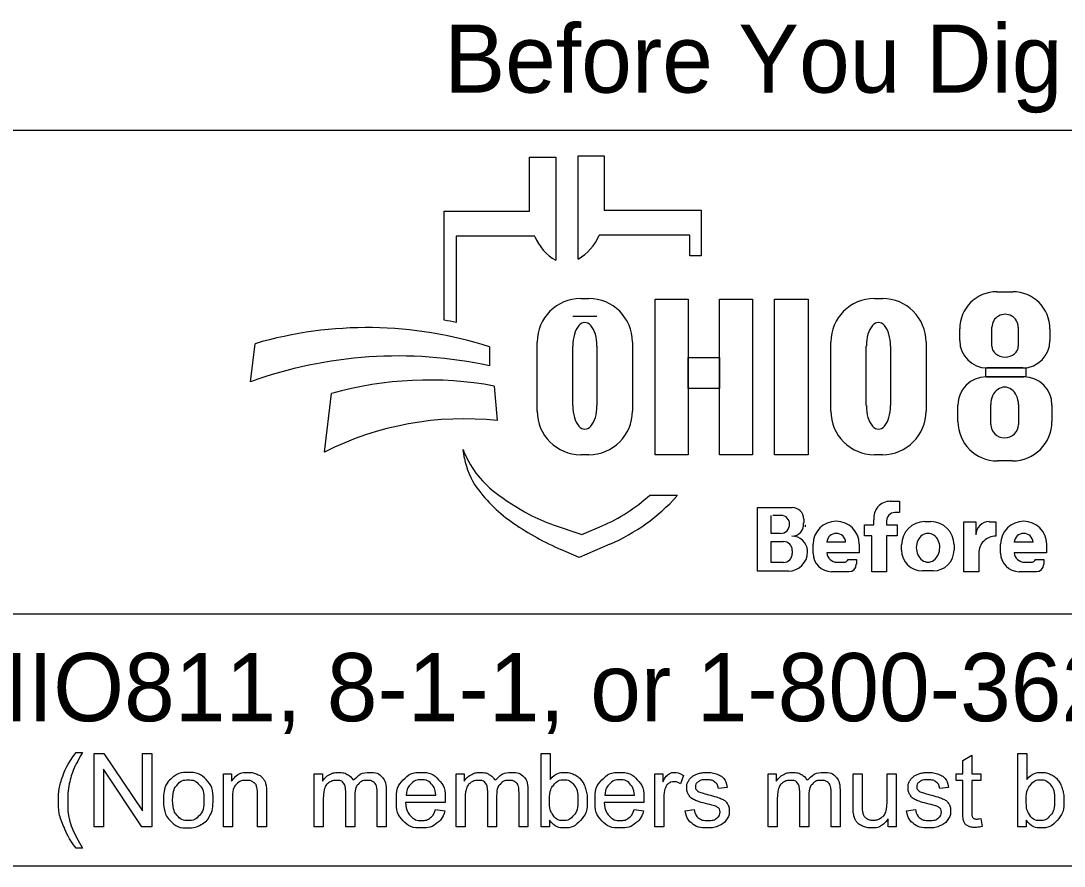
# Model space of a CAD drawing. Extents: x 0 to 34, y 0 to 22.
# Drawn here: x 2.689 to 4.831, y 2.143 to 3.88 of the extents above; entities that cross this region are included whole.
import ezdxf

# ---------------------------------------------------------------- set-up
doc = ezdxf.new("R2010")
doc.units = 0
doc.layers.add('GM_X_Minor_Lake', color=7, linetype='Continuous')
doc.layers.add('GM_X_Minor_Lake_Text', color=7, linetype='Continuous')

msp = doc.modelspace()

# ---------------------------------------------------------------- linework, layer by layer
at = {"layer": 'GM_X_Minor_Lake'}
for p, q in [((3.8329, 3.39), (3.8329, 3.6021)), ((3.8329, 3.6021), (3.8865, 3.6021)), ((3.8865, 3.6021), (3.8865, 3.4906)), ((3.7335, 3.4883), (3.7335, 3.5998)), ((3.7335, 3.5998), (3.7872, 3.5998)), ((3.7872, 3.5998), (3.7872, 3.3877)), ((3.5576, 3.2644), (3.5576, 3.4883)), ((3.5576, 3.4883), (3.7335, 3.4883)), ((3.8865, 3.4906), (4.0857, 3.4906)), ((4.0857, 3.4906), (4.0857, 3.3968)), ((3.5828, 3.4369), (3.5828, 3.26)), ((3.7439, 3.4369), (3.5828, 3.4369)), ((4.0625, 3.4392), (3.8761, 3.4392)), ((4.0625, 3.3968), (4.0625, 3.4392)), ((4.0857, 3.3968), (4.0625, 3.3968)), ((4.6931, 3.3231), (4.7258, 3.3231)), ((3.8385, 3.3091), (3.8551, 3.3091)), ((4.4416, 3.3091), (4.4581, 3.3091)), ((3.8718, 3.2721), (3.822, 3.2721)), ((4.6168, 3.2225), (4.6168, 3.2468)), ((4.683, 3.2111), (4.683, 3.2504)), ((4.7371, 3.2504), (4.7371, 3.2111)), ((4.8022, 3.2468), (4.8022, 3.2225)), ((3.1602, 3.1381), (3.1696, 3.2162)), ((3.7491, 3.0776), (3.7491, 3.2196)), ((3.9445, 3.2196), (3.9445, 3.0776)), ((4.3521, 3.0776), (4.3521, 3.2196)), ((4.5476, 3.2196), (4.5476, 3.0776)), ((3.6509, 3.2097), (3.6509, 3.1709)), ((3.822, 3.089), (3.822, 3.2114)), ((3.8718, 3.2114), (3.8718, 3.089)), ((4.425, 3.089), (4.425, 3.2114)), ((4.4748, 3.2114), (4.4748, 3.089)), ((4.7462, 3.1665), (4.6728, 3.1665)), ((3.6608, 3.1291), (3.6671, 3.0582)), ((4.671, 3.1482), (4.7483, 3.1482)), ((3.312, 2.9936), (3.3267, 3.1137)), ((4.6131, 3.0563), (4.6131, 3.0903)), ((4.6806, 3.0503), (4.6806, 3.0912)), ((4.7374, 3.0912), (4.7374, 3.0503)), ((4.8062, 3.0903), (4.8062, 3.0563)), ((3.5997, 2.9807), (3.5967, 2.9986)), ((3.8551, 2.9882), (3.8385, 2.9882)), ((4.4581, 2.9882), (4.4416, 2.9882)), ((4.7252, 2.9753), (4.6941, 2.9753)), ((3.98, 2.9048), (4.0375, 2.9048)), ((4.2013, 2.749), (4.2013, 2.8798)), ((4.2013, 2.8798), (4.2725, 2.8798)), ((4.4739, 2.8926), (4.4934, 2.8926)), ((4.4934, 2.8926), (4.4934, 2.8696)), ((4.2293, 2.8263), (4.2293, 2.8632)), ((4.2545, 2.8632), (4.2332, 2.8632)), ((4.2963, 2.856), (4.2963, 2.8481)), ((4.4406, 2.8442), (4.4406, 2.8546)), ((4.4667, 2.8526), (4.4667, 2.8442)), ((4.4934, 2.8691), (4.4832, 2.8691)), ((4.5451, 2.8508), (4.5573, 2.8508)), ((4.6254, 2.7478), (4.6254, 2.8505)), ((4.6254, 2.8505), (4.6499, 2.8505)), ((4.6499, 2.8505), (4.6499, 2.8237)), ((4.6772, 2.8505), (4.691, 2.8505)), ((4.691, 2.8505), (4.691, 2.8209)), ((3.7816, 2.8444), (3.841, 2.8239)), ((3.841, 2.8239), (3.8821, 2.8417)), ((4.4213, 2.8212), (4.4213, 2.8442)), ((4.4213, 2.8442), (4.4406, 2.8442)), ((4.4667, 2.8442), (4.4883, 2.8442)), ((4.4883, 2.8442), (4.4883, 2.8212)), ((4.2487, 2.8263), (4.2293, 2.8263)), ((4.2293, 2.7669), (4.2293, 2.8097)), ((4.2293, 2.8097), (4.2548, 2.8097)), ((4.3824, 2.8082), (4.3439, 2.8082)), ((4.4362, 2.8212), (4.4213, 2.8212)), ((4.4362, 2.7478), (4.4362, 2.8212)), ((4.4883, 2.8212), (4.4667, 2.8212)), ((4.4667, 2.8212), (4.4667, 2.7478)), ((4.7674, 2.8082), (4.7288, 2.8082)), ((3.835, 2.7769), (3.7976, 2.7934)), ((3.8983, 2.8044), (3.835, 2.7769)), ((4.2729, 2.7916), (4.2729, 2.7853)), ((4.3043, 2.7887), (4.3043, 2.7884)), ((4.3159, 2.7858), (4.3159, 2.8042)), ((4.4104, 2.7866), (4.344, 2.7866)), ((4.4104, 2.8042), (4.4104, 2.7866)), ((4.4973, 2.7922), (4.4973, 2.8029)), ((4.6051, 2.8029), (4.6051, 2.7922)), ((4.6559, 2.786), (4.6559, 2.7478)), ((4.7008, 2.7858), (4.7008, 2.8042)), ((4.7953, 2.7866), (4.7289, 2.7866)), ((4.7953, 2.8042), (4.7953, 2.7866)), ((4.2546, 2.7669), (4.2293, 2.7669)), ((4.3649, 2.7673), (4.379, 2.7673)), ((4.3876, 2.7729), (4.4045, 2.7729)), ((4.4045, 2.7729), (4.4045, 2.7631)), ((4.7498, 2.7673), (4.7639, 2.7673)), ((4.7725, 2.7729), (4.7894, 2.7729)), ((4.7894, 2.7729), (4.7894, 2.7631)), ((4.265, 2.749), (4.2013, 2.749)), ((4.3892, 2.7478), (4.3538, 2.7478)), ((4.4667, 2.7478), (4.4362, 2.7478)), ((4.5623, 2.7494), (4.5401, 2.7494)), ((4.6559, 2.7478), (4.6254, 2.7478)), ((4.7742, 2.7478), (4.7388, 2.7478))]:
    msp.add_line(p, q, dxfattribs=at)
for points in [[(3.991, 3.3081), (4.0589, 3.3081), (4.0589, 2.9881), (3.991, 2.9881)], [(4.1231, 3.3081), (4.1911, 3.3081), (4.1911, 2.9881), (4.1231, 2.9881)], [(4.2364, 3.3081), (4.3052, 3.3081), (4.3052, 2.9881), (4.2364, 2.9881)], [(4.0589, 3.1882), (4.1231, 3.1882), (4.1231, 3.1242), (4.0589, 3.1242)], [(4.6706, 3.1665), (4.7523, 3.1665), (4.7523, 3.1481), (4.6706, 3.1481)]]:
    msp.add_lwpolyline(points, close=True, dxfattribs=at)
for points in [[(2.8021, 2.3766), (2.8153, 2.3766)], [(2.8389, 2.2239), (2.8389, 2.3741), (2.8592, 2.3741), (2.9382, 2.2561), (2.9382, 2.3741), (2.9572, 2.3741), (2.9572, 2.2239), (2.9369, 2.2239), (2.8579, 2.3419), (2.8579, 2.2239), (2.8389, 2.2239)], [(3.7743, 2.2239), (3.7573, 2.2239), (3.7573, 2.3741), (3.7757, 2.3741), (3.7757, 2.3206)], [(4.6233, 2.2558), (4.6233, 2.3185), (4.6097, 2.3185), (4.6097, 2.3328), (4.6233, 2.3328), (4.6233, 2.3597), (4.6417, 2.3708), (4.6417, 2.3328), (4.6601, 2.3328), (4.6601, 2.3185), (4.6417, 2.3185), (4.6417, 2.2547)], [(4.7534, 2.2239), (4.7363, 2.2239), (4.7363, 2.3741), (4.7548, 2.3741), (4.7548, 2.3206)], [(3.1048, 2.2239), (3.1048, 2.3328), (3.1214, 2.3328), (3.1214, 2.3173)], [(3.2912, 2.2239), (3.2912, 2.3328), (3.3077, 2.3328), (3.3077, 2.3174)], [(3.5826, 2.2239), (3.5826, 2.3328), (3.5991, 2.3328), (3.5991, 2.3174)], [(3.9904, 2.2239), (3.9904, 2.3328), (4.007, 2.3328), (4.007, 2.3163)], [(4.0495, 2.3293), (4.043, 2.3122)], [(4.2236, 2.2239), (4.2236, 2.3328), (4.2401, 2.3328), (4.2401, 2.3174)], [(4.3979, 2.2654), (4.3979, 2.3328), (4.4164, 2.3328), (4.4164, 2.2724)], [(4.4676, 2.2745), (4.4676, 2.3328), (4.4861, 2.3328), (4.4861, 2.2239), (4.4696, 2.2239)], [(3.3743, 2.2871), (3.3743, 2.2239), (3.3559, 2.2239), (3.3559, 2.2946)], [(3.4388, 2.2986), (3.4388, 2.2239), (3.4203, 2.2239), (3.4203, 2.2924)], [(3.6657, 2.2871), (3.6657, 2.2239), (3.6473, 2.2239), (3.6473, 2.2946)], [(3.7301, 2.2986), (3.7301, 2.2239), (3.7117, 2.2239), (3.7117, 2.2924)], [(4.1394, 2.3046), (4.1213, 2.3022)], [(4.3067, 2.2871), (4.3067, 2.2239), (4.2883, 2.2239), (4.2883, 2.2946)], [(4.3711, 2.2986), (4.3711, 2.2239), (4.3527, 2.2239), (4.3527, 2.2924)], [(4.594, 2.3046), (4.5759, 2.3022)], [(3.1233, 2.2833), (3.1233, 2.2239), (3.1048, 2.2239)], [(3.1932, 2.2908), (3.1932, 2.2239), (3.1748, 2.2239), (3.1748, 2.2901)], [(3.3097, 2.2803), (3.3097, 2.2239), (3.2912, 2.2239)], [(3.56, 2.2736), (3.4788, 2.2736)], [(3.4799, 2.2887), (3.5406, 2.2887)], [(3.601, 2.2803), (3.601, 2.2239), (3.5826, 2.2239)], [(3.968, 2.2736), (3.8868, 2.2736)], [(3.8879, 2.2887), (3.9486, 2.2887)], [(4.0088, 2.2809), (4.0088, 2.2239), (3.9904, 2.2239)], [(4.242, 2.2803), (4.242, 2.2239), (4.2236, 2.2239)], [(3.5404, 2.2591), (3.5595, 2.2567)], [(3.9484, 2.2591), (3.9675, 2.2567)], [(4.053, 2.2564), (4.0712, 2.2593)], [(4.5076, 2.2564), (4.5258, 2.2593)], [(3.7743, 2.2375), (3.7743, 2.2239)], [(4.4696, 2.2239), (4.4696, 2.24)], [(4.6601, 2.2404), (4.6628, 2.2241)], [(4.7534, 2.2375), (4.7534, 2.2239)], [(2.8153, 2.1798), (2.8021, 2.1798)]]:
    msp.add_lwpolyline(points, dxfattribs=at)
for centre, radius, start, end in [((3.8353, 3.4736), 0.0985, 201.9296, 240.7469), ((3.7847, 3.476), 0.0985, 299.2531, 338.0704), ((4.6931, 3.2468), 0.0763, 90, 180), ((4.7258, 3.2468), 0.0763, 0, 90), ((3.8385, 3.2196), 0.0895, 90, 180), ((3.8551, 3.2196), 0.0895, 0, 90), ((4.4416, 3.2196), 0.0895, 90, 180), ((4.4581, 3.2196), 0.0895, 0, 90), ((3.4295, 2.4554), 0.8191, 79.2074, 81.0007), ((3.3997, 2.4302), 0.8191, 72.1402, 106.3144), ((4.6728, 3.2225), 0.056, 180, 270), ((4.7462, 3.2225), 0.056, 270, 0), ((3.4628, 2.2991), 0.8919, 77.8238, 109.8274), ((3.5267, 2.4094), 0.7322, 79.44, 105.8467), ((4.671, 3.0903), 0.0579, 90, 180), ((4.7483, 3.0903), 0.0579, 0, 90), ((3.8385, 3.0776), 0.0895, 180, 270), ((3.8551, 3.0776), 0.0895, 270, 0), ((4.4416, 3.0776), 0.0895, 180, 270), ((4.4581, 3.0776), 0.0895, 270, 0), ((3.5987, 2.4262), 0.6357, 83.8248, 116.8021), ((4.6941, 3.0563), 0.081, 180, 270), ((4.7252, 3.0563), 0.081, 270, 0), ((3.7841, 3.0707), 0.2008, 201.0457, 232.5314), ((3.741, 3.0048), 0.1433, 189.6817, 216.0884), ((3.8747, 3.1022), 0.3088, 216.0884, 235.7167), ((3.9766, 3.3219), 0.5173, 232.5314, 241.794), ((3.7387, 3.1722), 0.3602, 293.4582, 312.0712), ((3.7387, 3.1722), 0.401, 293.4582, 317.8286), ((4.2725, 2.856), 0.0238, 0, 90), ((4.4739, 2.859), 0.0335, 90, 187.5187), ((3.8914, 3.1631), 0.3371, 241.794, 250.9821), ((4.2505, 2.8463), 0.0169, 357.8325, 90), ((4.3631, 2.8042), 0.0473, 0, 180), ((4.4832, 2.8526), 0.0165, 90, 180), ((4.5451, 2.8029), 0.0478, 90, 180), ((4.5573, 2.8029), 0.0478, 0, 90), ((4.6768, 2.8237), 0.0269, 89.2449, 180), ((4.7481, 2.8042), 0.0473, 0, 180), ((4.0412, 3.3465), 0.6044, 235.7167, 246.2325), ((4.2487, 2.845), 0.0187, 270, 2.0582), ((4.2721, 2.8453), 0.0243, 270, 6.6529), ((4.2827, 2.8438), 0.0175, 347.4023, 0), ((4.2548, 2.7916), 0.0181, 0, 90), ((4.2722, 2.7889), 0.0321, 4.0748, 90), ((4.3632, 2.8072), 0.0193, 2.9632, 177.0368), ((4.6908, 2.786), 0.0349, 89.6033, 180), ((4.7481, 2.8072), 0.0193, 2.9632, 177.0368), ((4.265, 2.7884), 0.0393, 270, 0), ((4.2714, 2.7887), 0.033, 0, 11.7502), ((4.3538, 2.7858), 0.038, 180, 270), ((4.3649, 2.7883), 0.021, 184.827, 270), ((4.5401, 2.7922), 0.0428, 180, 270), ((4.5623, 2.7922), 0.0428, 270, 0), ((4.7388, 2.7858), 0.038, 180, 270), ((4.7498, 2.7883), 0.021, 184.827, 270), ((4.2546, 2.7853), 0.0184, 270, 0), ((4.379, 2.7767), 0.00938, 270, 335.9979), ((4.7639, 2.7767), 0.00938, 270, 335.9979), ((4.3892, 2.7631), 0.0152, 270, 0), ((4.7742, 2.7631), 0.0152, 270, 0)]:
    msp.add_arc(centre, radius, start, end, dxfattribs=at)
for centre, major_axis, ratio, start_param, end_param in [((3.8469, 3.2114), (0, 0.0484), 0.514403, 4.712389, 7.853982), ((4.4499, 3.2114), (0, 0.0484), 0.514403, 4.712389, 7.853982), ((4.71, 3.2504), (0.0271, 0), 0.969373, 0, 3.141593), ((4.71, 3.2111), (0.0271, 0), 0.818453, 3.141593, 6.283185), ((4.709, 3.0912), (0, 0.0358), 0.794529, 4.712389, 7.853982), ((3.8469, 3.089), (0, 0.0484), 0.514403, 1.570796, 4.712389), ((4.4499, 3.089), (0, 0.0484), 0.514403, 1.570796, 4.712389), ((4.709, 3.0503), (0.0284, 0), 0.959837, 3.141593, 6.283185), ((4.5517, 2.7976), (0, 0.029), 0.832186, 4.712389, 7.853982), ((4.5517, 2.7976), (0, 0.0302), 0.797287, 1.570796, 4.712389)]:
    msp.add_ellipse(centre, major_axis=major_axis, ratio=ratio, start_param=start_param, end_param=end_param, dxfattribs=at)
for points in [[(2.8021, 2.1798), (2.7869, 2.199), (2.7763, 2.2248), (2.7657, 2.2506), (2.7657, 2.2783), (2.7657, 2.3026), (2.7736, 2.325), (2.7829, 2.3509), (2.8021, 2.3766)], [(2.8153, 2.3766), (2.8029, 2.3553), (2.7989, 2.3462), (2.7927, 2.332), (2.7891, 2.3167), (2.7847, 2.2975), (2.7847, 2.2782), (2.7847, 2.2289), (2.8153, 2.1798)], [(2.9814, 2.2783), (2.9814, 2.3085), (2.9981, 2.3231), (3.0122, 2.3352), (3.0323, 2.3352), (3.0547, 2.3352), (3.069, 2.3205), (3.0832, 2.3058), (3.0832, 2.2799), (3.0832, 2.2589), (3.0769, 2.2469), (3.0706, 2.2348), (3.0586, 2.2282), (3.0466, 2.2215), (3.0323, 2.2215), (3.0095, 2.2215), (2.9954, 2.2362), (2.9814, 2.2508), (2.9814, 2.2783)], [(3.0003, 2.2783), (3.0003, 2.2574), (3.0094, 2.247), (3.0185, 2.2366), (3.0323, 2.2366), (3.046, 2.2366), (3.0551, 2.2471), (3.0642, 2.2575), (3.0642, 2.279), (3.0642, 2.2991), (3.0551, 2.3095), (3.0459, 2.3199), (3.0323, 2.3199), (3.0185, 2.3199), (3.0094, 2.3096), (3.0003, 2.2992), (3.0003, 2.2783)], [(3.1214, 2.3173), (3.1334, 2.3352), (3.156, 2.3352), (3.1659, 2.3352), (3.1741, 2.3316), (3.1823, 2.3281), (3.1864, 2.3224), (3.1905, 2.3166), (3.1922, 2.3087), (3.1932, 2.3036), (3.1932, 2.2908)], [(3.1748, 2.2901), (3.1748, 2.3013), (3.1726, 2.3069), (3.1705, 2.3125), (3.165, 2.3158), (3.1595, 2.3191), (3.1521, 2.3191), (3.1404, 2.3191), (3.1318, 2.3117), (3.1233, 2.3042), (3.1233, 2.2833)], [(3.3077, 2.3174), (3.3128, 2.3254), (3.3214, 2.3303), (3.3299, 2.3352), (3.3407, 2.3352), (3.3528, 2.3352), (3.3606, 2.3301), (3.3683, 2.3251), (3.3715, 2.3161), (3.3844, 2.3352), (3.4051, 2.3352), (3.4213, 2.3352), (3.43, 2.3262), (3.4388, 2.3172), (3.4388, 2.2986)], [(3.3559, 2.2946), (3.3559, 2.3069), (3.3514, 2.313), (3.3469, 2.3191), (3.3366, 2.3191), (3.3288, 2.3191), (3.3222, 2.315), (3.3156, 2.311), (3.3126, 2.3031), (3.3097, 2.2952), (3.3097, 2.2803)], [(3.4203, 2.2924), (3.4203, 2.3035), (3.4185, 2.3083), (3.4168, 2.3132), (3.412, 2.3162), (3.4073, 2.3191), (3.401, 2.3191), (3.3895, 2.3191), (3.3819, 2.3115), (3.3743, 2.3039), (3.3743, 2.2871)], [(3.5595, 2.2567), (3.555, 2.24), (3.5428, 2.2307), (3.5306, 2.2215), (3.5117, 2.2215), (3.4878, 2.2215), (3.4738, 2.2362), (3.4598, 2.2509), (3.4598, 2.2774), (3.4598, 2.3049), (3.474, 2.32), (3.4881, 2.3352), (3.5106, 2.3352), (3.5324, 2.3352), (3.5463, 2.3203), (3.5601, 2.3055), (3.5601, 2.2785), (3.5601, 2.2769), (3.56, 2.2736)], [(3.5406, 2.2887), (3.5394, 2.3025), (3.5337, 2.3094), (3.5249, 2.3201), (3.5108, 2.3201), (3.4981, 2.3201), (3.4894, 2.3115), (3.4808, 2.303), (3.4799, 2.2887)], [(3.5991, 2.3174), (3.6042, 2.3254), (3.6127, 2.3303), (3.6212, 2.3352), (3.6321, 2.3352), (3.6442, 2.3352), (3.6519, 2.3301), (3.6597, 2.3251), (3.6628, 2.3161), (3.6758, 2.3352), (3.6965, 2.3352), (3.7127, 2.3352), (3.7214, 2.3262), (3.7301, 2.3172), (3.7301, 2.2986)], [(3.6473, 2.2946), (3.6473, 2.3069), (3.6428, 2.313), (3.6383, 2.3191), (3.628, 2.3191), (3.6202, 2.3191), (3.6136, 2.315), (3.607, 2.311), (3.604, 2.3031), (3.601, 2.2952), (3.601, 2.2803)], [(3.7117, 2.2924), (3.7117, 2.3035), (3.7099, 2.3083), (3.7081, 2.3132), (3.7034, 2.3162), (3.6987, 2.3191), (3.6923, 2.3191), (3.6809, 2.3191), (3.6733, 2.3115), (3.6657, 2.3039), (3.6657, 2.2871)], [(3.7741, 2.2792), (3.7741, 2.2596), (3.7794, 2.2509), (3.7881, 2.2366), (3.8029, 2.2366), (3.815, 2.2366), (3.8238, 2.2471), (3.8326, 2.2576), (3.8326, 2.2784), (3.8326, 2.2998), (3.8241, 2.3099), (3.8157, 2.3201), (3.8038, 2.3201), (3.7917, 2.3201), (3.7829, 2.3096), (3.7741, 2.299), (3.7741, 2.2792)], [(3.7757, 2.3206), (3.7874, 2.3352), (3.8055, 2.3352), (3.8155, 2.3352), (3.8245, 2.3311), (3.8335, 2.3271), (3.8392, 2.3198), (3.845, 2.3124), (3.8483, 2.3021), (3.8516, 2.2918), (3.8516, 2.28), (3.8516, 2.252), (3.8378, 2.2368), (3.8239, 2.2215), (3.8046, 2.2215), (3.7853, 2.2215), (3.7743, 2.2375)], [(3.9675, 2.2567), (3.963, 2.24), (3.9508, 2.2307), (3.9386, 2.2215), (3.9196, 2.2215), (3.8958, 2.2215), (3.8818, 2.2362), (3.8678, 2.2509), (3.8678, 2.2774), (3.8678, 2.3049), (3.882, 2.32), (3.8961, 2.3352), (3.9186, 2.3352), (3.9404, 2.3352), (3.9543, 2.3203), (3.9681, 2.3055), (3.9681, 2.2785), (3.9681, 2.2769), (3.968, 2.2736)], [(3.9486, 2.2887), (3.9474, 2.3025), (3.9417, 2.3094), (3.9328, 2.3201), (3.9188, 2.3201), (3.9061, 2.3201), (3.8974, 2.3115), (3.8888, 2.303), (3.8879, 2.2887)], [(4.007, 2.3163), (4.0133, 2.3278), (4.0187, 2.3315), (4.0241, 2.3352), (4.0305, 2.3352), (4.0398, 2.3352), (4.0495, 2.3293)], [(4.043, 2.3122), (4.0363, 2.3162), (4.0295, 2.3162), (4.0235, 2.3162), (4.0187, 2.3125), (4.0139, 2.3089), (4.0119, 2.3024), (4.0088, 2.2926), (4.0088, 2.2809)], [(4.1213, 2.3022), (4.1201, 2.3106), (4.1142, 2.3153), (4.1083, 2.3201), (4.0975, 2.3201), (4.0848, 2.3201), (4.0794, 2.3159), (4.0739, 2.3116), (4.0739, 2.306), (4.0739, 2.3024), (4.0762, 2.2995), (4.0785, 2.2966), (4.0833, 2.2946), (4.086, 2.2936), (4.0996, 2.2899), (4.1192, 2.2847), (4.1269, 2.2813), (4.1347, 2.278), (4.1391, 2.2717), (4.1435, 2.2653), (4.1435, 2.2559), (4.1435, 2.2467), (4.1381, 2.2386), (4.1327, 2.2304), (4.1226, 2.226), (4.1124, 2.2215), (4.0996, 2.2215), (4.0784, 2.2215), (4.0672, 2.2303), (4.0561, 2.2391), (4.053, 2.2564)], [(4.0712, 2.2593), (4.0727, 2.2483), (4.0798, 2.2425), (4.0868, 2.2366), (4.0995, 2.2366), (4.1122, 2.2366), (4.1184, 2.2418), (4.1245, 2.247), (4.1245, 2.254), (4.1245, 2.2602), (4.1191, 2.2638), (4.1153, 2.2663), (4.1002, 2.2701), (4.0799, 2.2752), (4.072, 2.2789), (4.0642, 2.2827), (4.0601, 2.2893), (4.0561, 2.2959), (4.0561, 2.3038), (4.0561, 2.3111), (4.0594, 2.3173), (4.0628, 2.3235), (4.0685, 2.3276), (4.0728, 2.3308), (4.0803, 2.333), (4.0877, 2.3352), (4.0962, 2.3352), (4.109, 2.3352), (4.1187, 2.3315), (4.1284, 2.3278), (4.133, 2.3215), (4.1377, 2.3152), (4.1394, 2.3046)], [(4.2401, 2.3174), (4.2452, 2.3254), (4.2537, 2.3303), (4.2622, 2.3352), (4.2731, 2.3352), (4.2852, 2.3352), (4.2929, 2.3301), (4.3007, 2.3251), (4.3038, 2.3161), (4.3168, 2.3352), (4.3375, 2.3352), (4.3537, 2.3352), (4.3624, 2.3262), (4.3711, 2.3172), (4.3711, 2.2986)], [(4.2883, 2.2946), (4.2883, 2.3069), (4.2838, 2.313), (4.2793, 2.3191), (4.269, 2.3191), (4.2612, 2.3191), (4.2546, 2.315), (4.248, 2.311), (4.245, 2.3031), (4.242, 2.2952), (4.242, 2.2803)], [(4.3527, 2.2924), (4.3527, 2.3035), (4.3509, 2.3083), (4.3491, 2.3132), (4.3444, 2.3162), (4.3397, 2.3191), (4.3333, 2.3191), (4.3219, 2.3191), (4.3143, 2.3115), (4.3067, 2.3039), (4.3067, 2.2871)], [(4.5759, 2.3022), (4.5747, 2.3106), (4.5688, 2.3153), (4.5629, 2.3201), (4.5521, 2.3201), (4.5394, 2.3201), (4.5339, 2.3159), (4.5285, 2.3116), (4.5285, 2.306), (4.5285, 2.3024), (4.5308, 2.2995), (4.533, 2.2966), (4.5378, 2.2946), (4.5406, 2.2936), (4.5542, 2.2899), (4.5737, 2.2847), (4.5815, 2.2813), (4.5893, 2.278), (4.5937, 2.2717), (4.5981, 2.2653), (4.5981, 2.2559), (4.5981, 2.2467), (4.5927, 2.2386), (4.5873, 2.2304), (4.5772, 2.226), (4.567, 2.2215), (4.5542, 2.2215), (4.5329, 2.2215), (4.5218, 2.2303), (4.5107, 2.2391), (4.5076, 2.2564)], [(4.5258, 2.2593), (4.5273, 2.2483), (4.5343, 2.2425), (4.5414, 2.2366), (4.554, 2.2366), (4.5668, 2.2366), (4.5729, 2.2418), (4.5791, 2.247), (4.5791, 2.254), (4.5791, 2.2602), (4.5736, 2.2638), (4.5698, 2.2663), (4.5548, 2.2701), (4.5345, 2.2752), (4.5266, 2.2789), (4.5188, 2.2827), (4.5147, 2.2893), (4.5107, 2.2959), (4.5107, 2.3038), (4.5107, 2.3111), (4.514, 2.3173), (4.5173, 2.3235), (4.5231, 2.3276), (4.5274, 2.3308), (4.5348, 2.333), (4.5423, 2.3352), (4.5508, 2.3352), (4.5636, 2.3352), (4.5733, 2.3315), (4.583, 2.3278), (4.5876, 2.3215), (4.5922, 2.3152), (4.594, 2.3046)], [(4.7532, 2.2792), (4.7532, 2.2596), (4.7585, 2.2509), (4.7672, 2.2366), (4.782, 2.2366), (4.7941, 2.2366), (4.8029, 2.2471), (4.8116, 2.2576), (4.8116, 2.2784), (4.8116, 2.2998), (4.8032, 2.3099), (4.7948, 2.3201), (4.7828, 2.3201), (4.7708, 2.3201), (4.762, 2.3096), (4.7532, 2.299), (4.7532, 2.2792)], [(4.7548, 2.3206), (4.7664, 2.3352), (4.7846, 2.3352), (4.7946, 2.3352), (4.8036, 2.3311), (4.8125, 2.3271), (4.8183, 2.3198), (4.8241, 2.3124), (4.8274, 2.3021), (4.8306, 2.2918), (4.8306, 2.28), (4.8306, 2.252), (4.8168, 2.2368), (4.803, 2.2215), (4.7836, 2.2215), (4.7644, 2.2215), (4.7534, 2.2375)], [(3.4788, 2.2736), (3.4799, 2.2557), (3.489, 2.2462), (3.4981, 2.2366), (3.5117, 2.2366), (3.5219, 2.2366), (3.5291, 2.242), (3.5362, 2.2473), (3.5404, 2.2591)], [(3.8868, 2.2736), (3.8879, 2.2557), (3.897, 2.2462), (3.9061, 2.2366), (3.9197, 2.2366), (3.9299, 2.2366), (3.937, 2.242), (3.9442, 2.2473), (3.9484, 2.2591)], [(4.4164, 2.2724), (4.4164, 2.258), (4.4175, 2.253), (4.4192, 2.2457), (4.4249, 2.2416), (4.4305, 2.2374), (4.4388, 2.2374), (4.4471, 2.2374), (4.4543, 2.2417), (4.4616, 2.2459), (4.4646, 2.2533), (4.4676, 2.2606), (4.4676, 2.2745)], [(4.4696, 2.24), (4.4569, 2.2215), (4.4351, 2.2215), (4.4255, 2.2215), (4.4171, 2.2252), (4.4088, 2.2289), (4.4047, 2.2345), (4.4007, 2.2401), (4.3991, 2.2482), (4.3979, 2.2536), (4.3979, 2.2654)], [(4.6628, 2.2241), (4.655, 2.2224), (4.6488, 2.2224), (4.6388, 2.2224), (4.6333, 2.2256), (4.6278, 2.2288), (4.6255, 2.234), (4.6233, 2.2392), (4.6233, 2.2558)], [(4.6417, 2.2547), (4.6417, 2.2468), (4.6427, 2.2445), (4.6436, 2.2423), (4.6458, 2.2409), (4.648, 2.2396), (4.6521, 2.2396), (4.6551, 2.2396), (4.6601, 2.2404)]]:
    msp.add_open_spline(points, degree=3, dxfattribs=at)
at = {"layer": 'GM_X_Minor_Lake_Text'}
for p, q in [((2.3775, 3.6553), (6.6275, 3.6553)), ((6.6275, 2.6607), (2.3775, 2.6607)), ((6.6275, 2.1428), (2.3775, 2.1428))]:
    msp.add_line(p, q, dxfattribs=at)

# ---------------------------------------------------------------- texts
at = {"layer": 'GM_X_Minor_Lake'}
for s, p in [('Before You Dig', (3.5583, 3.7321)), ('OHIO811, 8-1-1, or 1-800-362-2764', (2.422, 2.4406))]:
    msp.add_text(s, height=0.14, dxfattribs=at).set_placement(p)

doc.saveas('drawing.dxf')
